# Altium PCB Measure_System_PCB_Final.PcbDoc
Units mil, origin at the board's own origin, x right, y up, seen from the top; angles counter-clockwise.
Board outline 4890.03 x 2230.03 mil, 2 copper layers (Top Layer, Bottom Layer); 44 components, 29 nets, 115 pads, 0 vias.
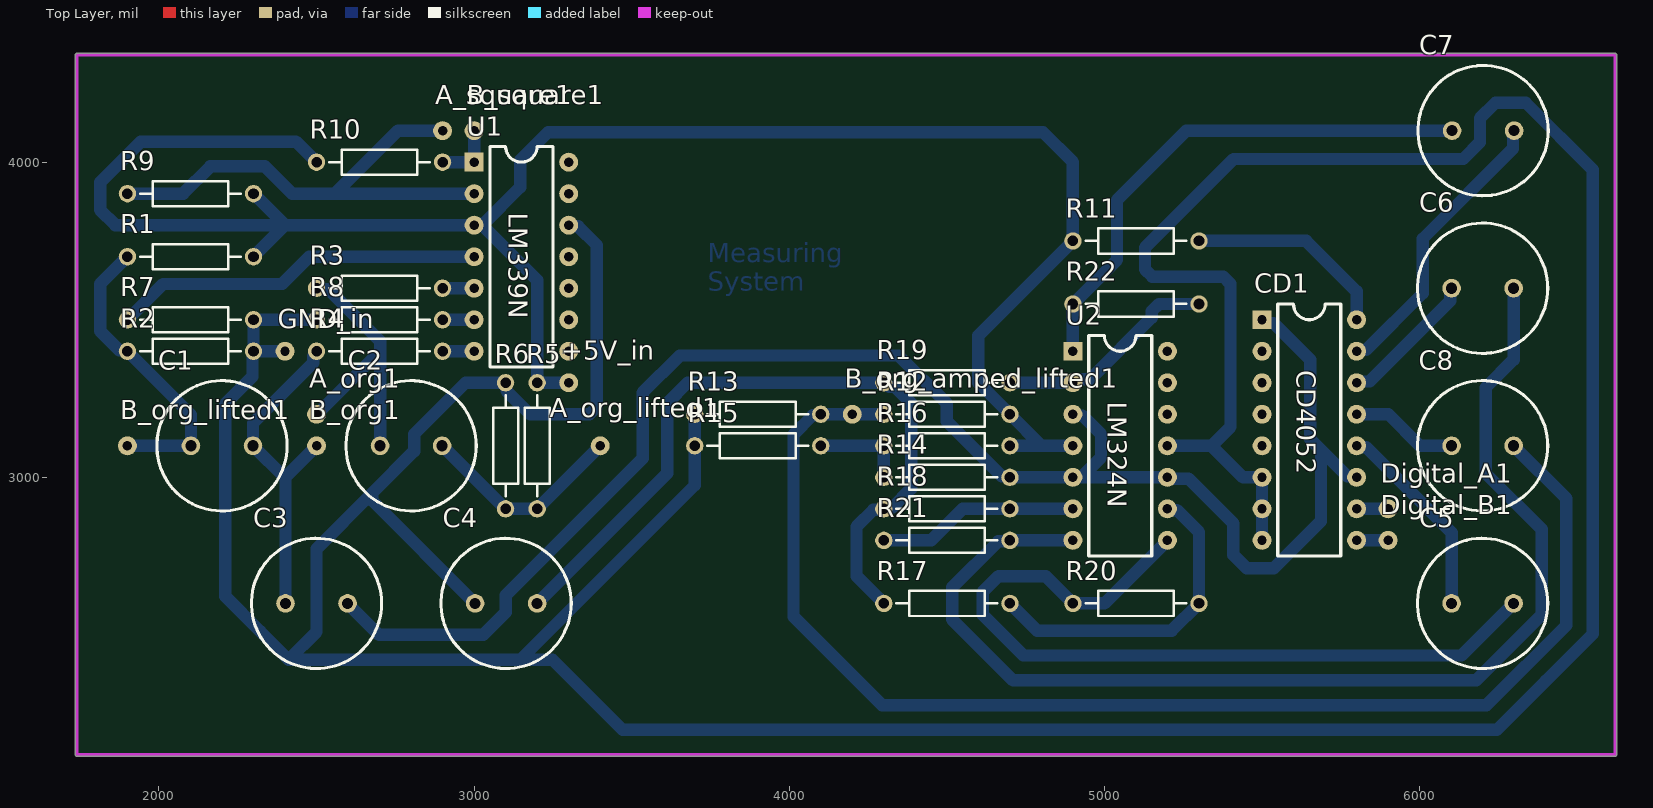
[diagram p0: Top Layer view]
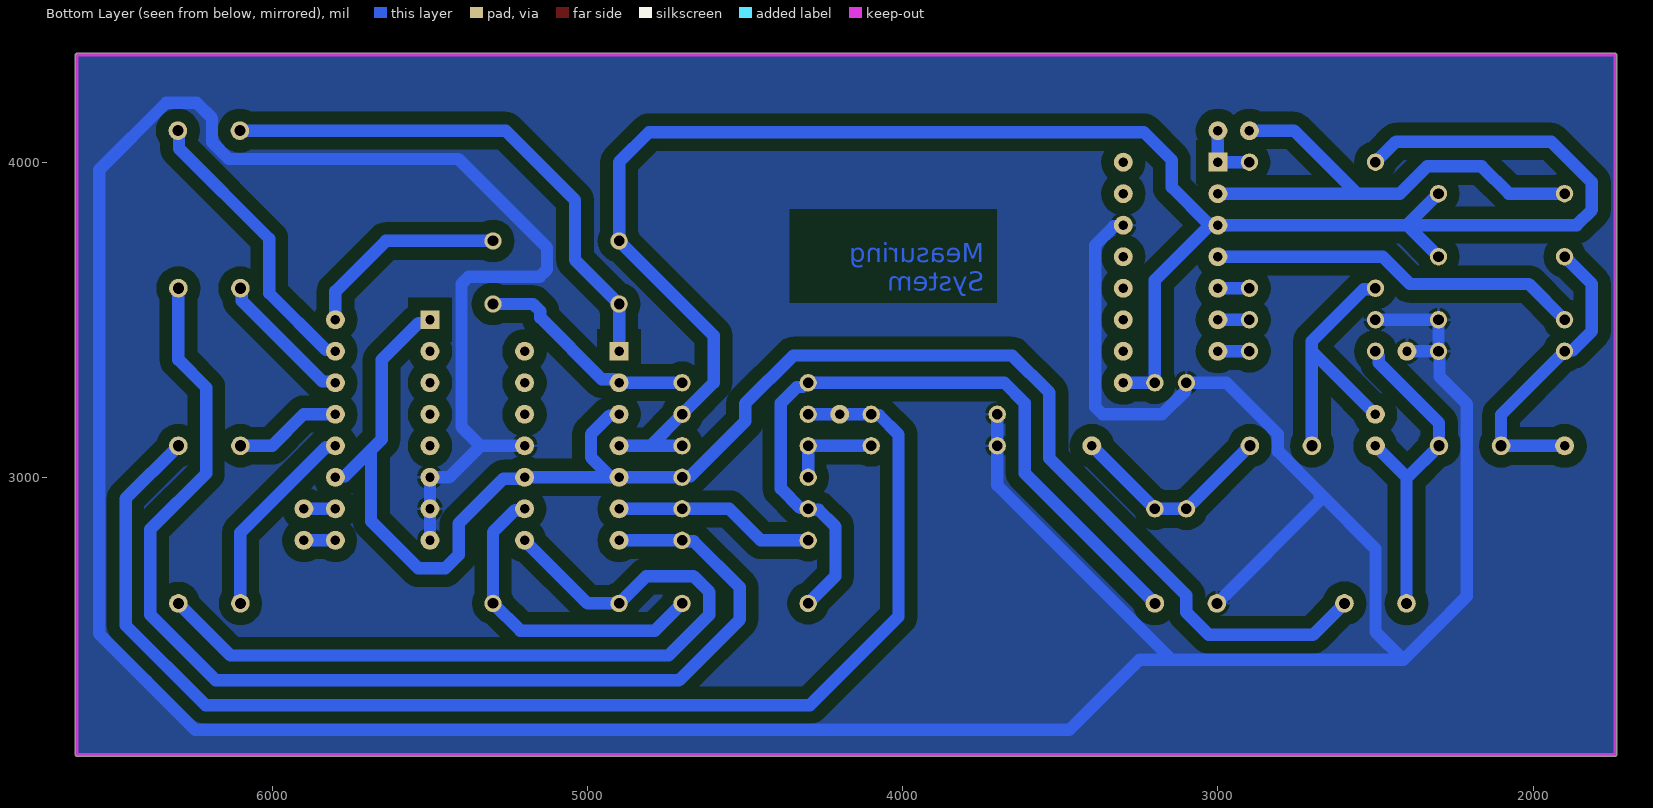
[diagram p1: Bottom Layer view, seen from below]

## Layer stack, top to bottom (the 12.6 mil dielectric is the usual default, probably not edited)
Top Solder: solder mask 0.4, Solder Resist, Dk 3.5
Top Layer: signal copper 1.4
Dielectric 1: dielectric 12.6, FR-4, Dk 4.8
Bottom Layer: signal copper 1.4
Bottom Solder: solder mask 0.4, Solder Resist, Dk 3.5

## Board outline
1734.98,2120 1734.99,4339.97 cw(c1740,4340) 1740,4345.01 6620,4345.02 cw(c6620,4340) 6625.02,4340 6625.02,2120 cw(c6620,2120) 6620,2114.99 1740,2114.98 cw(c1740,2120)

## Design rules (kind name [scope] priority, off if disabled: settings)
Clearance [All] p1: gap=39.37 ignorepadtopadclearanceinfootprint=FALSE
PolygonConnect [All] p1: connectstyle=Relief reliefconductorwidth=10 reliefentries=4 polygonreliefangle="90 Angle" airgapwidth=10
RoutingVias [All] p1: holewidth=28 width=50 viastyle="Through Hole" minholewidth=28 minwidth=50 maxholewidth=28 maxwidth=50
SolderMaskExpansion [All] p1: expansion=4 istentingtop=FALSE
Width [All] p1: maxlimit=393.7 minlimit=19.68 preferedwidth=39.37 toplayer_maxwidth=393.7 bottomlayer_prefwidth=39.37 minimp=50.000000 maximp=50.000000 favimp=50.000000
30 further rules are at their usual default settings.

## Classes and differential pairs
component class Part_Square: C1 C2 R1 R2 R3 R4 R5 R6 R7 R8 R9 R10 U1
component class Part_PGA: C3 C4 C5 C6 C7 C8 R11 R12 R13 R14 R15 R16 R17 R18 R19 R20 R21 R22 U2
component class Measure_System_Main: +5V_in A_org1 A_org_lifted1 A_square1 B_org1 B_org_amped_lifted1 B_org_lifted1 B_square1 Digital_B1 GND_in

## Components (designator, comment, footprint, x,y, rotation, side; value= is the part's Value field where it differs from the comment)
+5V_in "Hole" Hole 3300,3300 r90 top
A_org1 "Hole" Hole 2500,3200 r90 top
A_org_lifted1 "Hole" Hole 3400,3100 r90 top
A_square1 "Hole" Hole 2900,4100 r90 top
B_org1 "Hole" Hole 2500,3100 r90 top
B_org_amped_lifted1 "Hole" Hole 4200,3200 r90 top
B_org_lifted1 "Hole" Hole 1900,3100 r90 top
B_square1 "Hole" Hole 3000,4100 r90 top
C1 "Cap Pol1" RB5-10.5 2200,3100 r180 top value=10u
C2 "Cap Pol1" RB5-10.5 2800,3100 r0 top value=10u
C3 "Cap Pol1" RB5-10.5 2500,2600 r0 top value=10u
C4 "Cap Pol1" RB5-10.5 3101.57,2600 r0 top value=10u
C5 "Cap Pol1" RB5-10.5 6200,2600 r180 top value=10u
C6 "Cap Pol1" RB5-10.5 6200,3600 r180 top value=10u
C7 "Cap Pol1" RB5-10.5 6201.57,4100 r0 top value=10u
C8 "Cap Pol1" RB5-10.5 6200,3100 r0 top value=10u
CD1 "CD4052" CD4052 5500,3500 r0 top
Digital_A1 "Hole" Hole 5900,2900 r90 top
Digital_B1 "Hole" Hole 5900,2800 r90 top
GND_in "Hole" Hole 2400,3400 r90 top
R1 "Res2" AXIAL-0.4 2100,3700 r0 top value=100k
R2 "Res2" AXIAL-0.4 2100,3400 r180 top value=100k
R3 "Res2" AXIAL-0.4 2700,3600 r180 top value=1k
R4 "Res2" AXIAL-0.4 2700,3400 r180 top value=1k
R5 "Res2" AXIAL-0.4 3200,3100 r90 top value=100k
R6 "Res2" AXIAL-0.4 3100,3100 r270 top value=100k
R7 "Res2" AXIAL-0.4 2100,3500 r180 top value=10k
R8 "Res2" AXIAL-0.4 2700,3500 r180 top value=10k
R9 "Res2" AXIAL-0.4 2100,3900 r180 top value=10k
R10 "Res2" AXIAL-0.4 2700,4000 r180 top value=10k
R11 "Res2" AXIAL-0.4 5100,3750 r180 top value=200
R12 "Res2" AXIAL-0.4 4500,3200 r0 top value=100k
R13 "Res2" AXIAL-0.4 3900,3200 r0 top value=100k
R14 "Res2" AXIAL-0.4 4500,3000 r0 top value=100k
R15 "Res2" AXIAL-0.4 3900,3100 r0 top value=100k
R16 "Res2" AXIAL-0.4 4500,3100 r180 top value=100k
R17 "Res2" AXIAL-0.4 4500,2600 r0 top value=50k
R18 "Res2" AXIAL-0.4 4500,2900 r0 top value=24k
R19 "Res2" AXIAL-0.4 4500,3300 r0 top value=12k
R20 "Res2" AXIAL-0.4 5100,2600 r180 top value=100k
R21 "Res2" AXIAL-0.4 4500,2800 r0 top value=100k
R22 "Res2" AXIAL-0.4 5100,3550 r180 top value=100k
U1 "LM339N" LM339N 3000,4000 r0 top
U2 "LM324N" LM324N 4900,3400 r0 top

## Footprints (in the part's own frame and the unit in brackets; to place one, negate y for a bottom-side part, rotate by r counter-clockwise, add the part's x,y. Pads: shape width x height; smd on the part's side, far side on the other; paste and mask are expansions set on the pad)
AXIAL-0.4 [mm] "Axial Device, Thru-Hole; 2 Leads; 0.4 in Pin Spacing"
  round 1.4 hole 0.85: 1(-5.08,0) 2(5.08,0)
  silkscreen extent -4.06,-1.02 4.06,1.02
CD4052 [mil]
  rect 60x60 hole 30: 1(0,0)
  round 60 hole 30 mask+4: 2(0,-100) 3(0,-200) 4(0,-300) 5(0,-400) 6(0,-500) 7(0,-600) 8(0,-700) 9(300,-700) 10(300,-600) 11(300,-500) 12(300,-400) 13(300,-300) 14(300,-200) 15(300,-100) 16(300,0)
  silkscreen extent 50,-750 250,50
Hole [mil]
  round 60 hole 30 mask+4: 1(0,0)
LM324N [mil]
  rect 60x60 hole 30: 1(0,0)
  round 60 hole 30 mask+4: 2(0,-100) 3(0,-200) 4(0,-300) 5(0,-400) 6(0,-500) 7(0,-600) 8(300,-600) 9(300,-500) 10(300,-400) 11(300,-300) 12(300,-200) 13(300,-100) 14(300,0)
  silkscreen extent 50,-650 250,50
LM339N [mil]
  rect 60x60 hole 30: 1(0,0)
  round 60 hole 30 mask+4: 2(0,-100) 3(0,-200) 4(0,-300) 5(0,-400) 6(0,-500) 7(0,-600) 8(300,-600) 9(300,-500) 10(300,-400) 11(300,-300) 12(300,-200) 13(300,-100) 14(300,0)
  silkscreen extent 50,-650 250,50
RB5-10.5 [mm] "Capacitor (Radial); 2 Leads"
  round 1.5 hole 0.9: 1(-2.5,0) 2(2.5,0)
  silkscreen extent -5.25,-5.25 5.25,5.25

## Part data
C1 C2 C3 C4 C5 C6 C7 C8: "Polarized Capacitor (Radial)"
R1 R2 R3 R4 R5 R6 R7 R8 R9 R10 R11 R12 R13 R14 R15 R16 R17 R18 R19 R20 R21 R22: "Resistor"

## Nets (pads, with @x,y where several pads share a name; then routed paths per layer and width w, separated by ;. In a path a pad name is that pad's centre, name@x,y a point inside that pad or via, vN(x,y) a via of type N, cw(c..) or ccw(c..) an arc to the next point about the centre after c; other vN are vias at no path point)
+5: +5V_in.1 R1.2 R5.2 R9.1 R10.2 R11.2 R12.2 R16.1 U1.3 U2.4 | length 6429.8
  Bottom Layer w39.37: R1.2 2400,3800 ; R9.1 2400,3800 ; R10.2 2434.65,4065.35 1942.86,4065.35 1813.39,3935.88 1813.39,3848.43 1861.82,3800 2400,3800 ; 3029.89,3796.05 3200,3625.94 R5.2 +5V_in.1 ; R16.1 4800,3100 ; U2.4 4800,3100 ; 2400,3800 U1.3 3003.95,3803.95 3029.89,3803.95 3146.5,3920.56 3146.5,4006.5 3235,4095 4805,4095 4900,4000 R11.2 4600,3450 4600,3300 R12.2 4800,3100
B_org: B_org1.1 C1.1 C3.1 R4.2 | length 1209.3
  Bottom Layer w39.37: C3.1 2401.57,3001.57 B_org1.1 2399.21,2999.21 C1.1 2298.43,3172.48 2489.06,3363.11 2489.06,3384.79 2500,3395.74 R4.2
B_org_amp_1: C3.2 CD1.1 CD1.11 R14.2 U2.3 U2.5 U2.10 | length 5223.3
  Bottom Layer w39.37: C3.2 2698.43,2500 3028.64,2500 3100,2571.36 3100,2625.27 3534.65,3059.92 3534.65,3268.49 3652.77,3386.61 4347.23,3386.61 4500,3233.85 4500,3177.51 4600,3077.51 4674.5,3003.01 4696.99,3003.01 R14.2 U2.5 U2.10 5203.95,2996.05 5266.65,2996.05 5409.2,2853.5 5409.2,2753.5 5451.76,2710.94 5536.89,2710.94 5687.03,2861.09 5687.03,3087.03 ; U2.3 4903.95,3196.05 4929.89,3196.05 4989.06,3136.89 4989.06,3063.11 4929.89,3003.95 ; CD1.1@5510.31,3489.68 5536.26,3489.68 5653.5,3372.44 5653.5,3120.56 5687.03,3087.03 ; CD1.11 5796.05,3003.95 5770.11,3003.95 5687.03,3087.03
B_org_amp_2.5: C5.2 CD1.12 | length 640.1
  Bottom Layer w39.37: CD1.12 5803.95,3096.05 5829.89,3096.05 6101.57,2824.37 C5.2
B_org_amp_5: C6.2 CD1.14 | length 446.8
  Bottom Layer w39.37: CD1.14 5803.95,3303.95 5841.25,3303.95 6097.81,3560.51 6097.81,3596.23 C6.2
B_org_amp_10: C7.2 CD1.15 | length 922.3
  Bottom Layer w39.37: CD1.15 5803.95,3403.95 5829.89,3403.95 6010,3584.06 6010,3756.91 6296.23,4043.15 6296.23,4096.23 C7.2
B_org_amped: C8.1 CD1.13 | length 343
  Bottom Layer w39.37: CD1.13 5900.92,3200 6000.92,3100 C8.1
Digital_A: CD1.10 Digital_A1.1 | length 100
  Bottom Layer w39.37: CD1.10 Digital_A1.1
Digital_B: CD1.9 Digital_B1.1 | length 100
  Bottom Layer w39.37: CD1.9 Digital_B1.1
GND: C4.1 CD1.6 CD1.7 CD1.8 GND_in.1 R2.1 R6.1 R7.1 R8.2 R13.1 R15.1 U1.12 U2.11 | length 14199.2
  Bottom Layer w39.37: GND_in.1 R2.1 ; R8.2 R7.1 R2.1 ; C4.1 2676.85,2926.3 2676.85,2950 ; R6.1 2973.15,3300 2809.84,3136.69 2809.84,3082.99 2676.85,2950 ; R6.1@3103.01,3274.5 3177.51,3200 3365.99,3200 3389.06,3223.06 3389.06,3736.89 3329.89,3796.05 3303.95,3796.05 U1.12 ; R13.1 R15.1 3700,2974.73 3146.53,2421.26 ; U2.11 5340,3100 ; CD1.8 CD1.7 CD1.6 5440,3000 5340,3100 ; R2.1 2296.99,3396.99 2296.99,3319.48 2209.84,3232.33 2209.84,2623.06 2321.49,2511.42 2411.65,2421.26 ; 2411.65,2421.26 3146.53,2421.26 ; 2411.65,2421.26 2500,2509.61 2500,2773.15 2676.85,2950 ; 3146.53,2421.26 3248.74,2421.26 3471.57,2198.43 6244.84,2198.43 6400.35,2353.94 6550,2503.59 6550,3975.27 6336.69,4188.58 6240.74,4188.58 6191.73,4139.57 6191.73,4063.31 6138.42,4010 6130,4010 5410,4010 5128.74,3728.74 5128.74,3659.68 5151.8,3636.61 5376.94,3636.61 5400,3613.55 5400,3160 5340,3100
NetA_org1_1: A_org1.1 C2.1 R3.2 | length 887.7
  Bottom Layer w39.37: A_org1.1 2501.57,3200 2701.57,3400 ; R3.2 2503.01,3596.99 2536.86,3596.99 2701.57,3432.27 2701.57,3400 ; C2.1 2701.57,3400
NetA_org_lifted1_1: A_org_lifted1.1 C2.2 R5.1 R6.2 | length 667.3
  Bottom Layer w39.37: C2.2 2899.21,3100 3099.21,2900 R6.2 R5.1 A_org_lifted1.1
NetA_square1_1: A_square1.1 R9.2 U1.2 | length 1596.1
  Bottom Layer w39.37: R9.2 2076.76,3900 2163.38,3986.61 2335.88,3986.61 2422.49,3900 2558.45,3900 ; A_square1.1 2758.45,4100 2558.45,3900 ; U1.2 2558.45,3900
NetB_org_amped_lifted1_1: B_org_amped_lifted1.1 C8.2 R12.1 R13.2 | length 4203.4
  Bottom Layer w39.37: R12.1 B_org_amped_lifted1.1 R13.2 4096.99,3196.99 4074.5,3196.99 4013.39,3135.88 4013.39,2557.97 4294.19,2277.17 6212.22,2277.17 6465.75,2530.69 6465.75,2932.68 C8.2
NetB_org_lifted1_1: B_org_lifted1.1 C1.2 R1.1 R2.2 | length 943.2
  Bottom Layer w39.37: R2.2@1874.5,3403.01 1813.39,3464.12 1813.39,3613.39 R1.1 ; B_org_lifted1.1 C1.2 2101.57,3198.43 R2.2
NetB_square1_1: B_square1.1 R10.1 U1.1 | length 200
  Bottom Layer w39.37: R10.1 U1.1 B_square1.1
NetC4_2: C4.2 R17.1 R18.1 R19.1 | length 2381
  Bottom Layer w39.37: C4.2 3613.39,3013.39 3613.39,3235.88 3677.51,3300 4304.26,3300 4317.65,3286.61 4335.88,3286.61 4386.61,3235.88 4386.61,2964.12 R18.1@4325.5,2903.01 ; R17.1 4213.39,2686.61 4213.39,2843.51 4266.86,2896.99 4296.99,2896.99 R18.1
NetC5_1: C5.1 R20.2 U2.8 | length 2605.3
  Bottom Layer w39.37: U2.8 5000,2600 R20.2 4813.39,2686.61 4664.12,2686.61 4613.39,2635.88 4613.39,2564.12 4742.86,2434.65 6133.07,2434.65 C5.1
NetC6_1: C6.1 R21.2 U2.7 | length 3729.4
  Bottom Layer w39.37: U2.7 4695.74,2800 4692.73,2796.99 4663.14,2796.99 4516.71,2650.55 4516.71,2549.45 4710.25,2355.91 6179.61,2355.91 6387.01,2563.31 6387.01,2835.42 6209.84,3012.59 6209.84,3284.7 6298.43,3373.28 C6.1
NetC7_1: C7.1 R22.2 U2.1 | length 1692.3
  Bottom Layer w39.37: U2.1 R22.2 5040,3690 5040,3880 5260,4100 C7.1
NetCD1_16: CD1.16 R11.1 | length 656.3
  Bottom Layer w39.37: R11.1 5640,3750 5800,3590 CD1.16
NetR3_1: R3.1 U1.5 | length 100
  Bottom Layer w39.37: R3.1 U1.5
NetR4_1: R4.1 U1.7 | length 100
  Bottom Layer w39.37: R4.1 U1.7
NetR7_2: R7.2 U1.4 | length 1182.8
  Bottom Layer w39.37: R7.2 2013.39,3613.39 2390.89,3613.39 2477.51,3700 U1.4
NetR8_1: R8.1 U1.6 | length 100
  Bottom Layer w39.37: R8.1 U1.6
NetR14_1: R14.1 R15.2 R16.2 | length 300
  Bottom Layer w39.37: R15.2 R16.2 R14.1
NetR17_2: R17.2 R20.1 U2.9 | length 1028.4
  Bottom Layer w39.37: R17.2 4786.61,2513.39 5213.39,2513.39 R20.1 5300,2825.94 5229.89,2896.05 5203.95,2896.05 U2.9
NetR18_2: R18.2 R21.1 U2.6 | length 647
  Bottom Layer w39.37: R21.1 4450,2800 4550,2900 R18.2 U2.6 U2.6@4896.05,2896.05
NetR19_2: R19.2 R22.1 U2.2 | length 712.2
  Bottom Layer w39.37: R19.2@4705.68,3305.68 4711.36,3300 U2.2 4905.58,3300 4916.53,3310.94 4954.46,3310.94 5150,3506.48 5150,3526.94 5173.06,3550 R22.1
pads on no net: CD1.2 CD1.3 CD1.4 CD1.5 U1.8 U1.9 U1.10 U1.11 U1.13 U1.14 U2.12 U2.13 U2.14

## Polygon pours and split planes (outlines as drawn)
GND on Bottom Layer "NONET" (solid, pour order 0): 6620,4340 6620,2120 1740,2120 1740,4340

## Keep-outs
Keep-Out Layer:
  lines w10: 1740,2120 1740,4340 6620,4340 6620,2120 1740,2120

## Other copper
Bottom Layer:
  text "Measuring / System" at 3741.17,3592.6 h60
